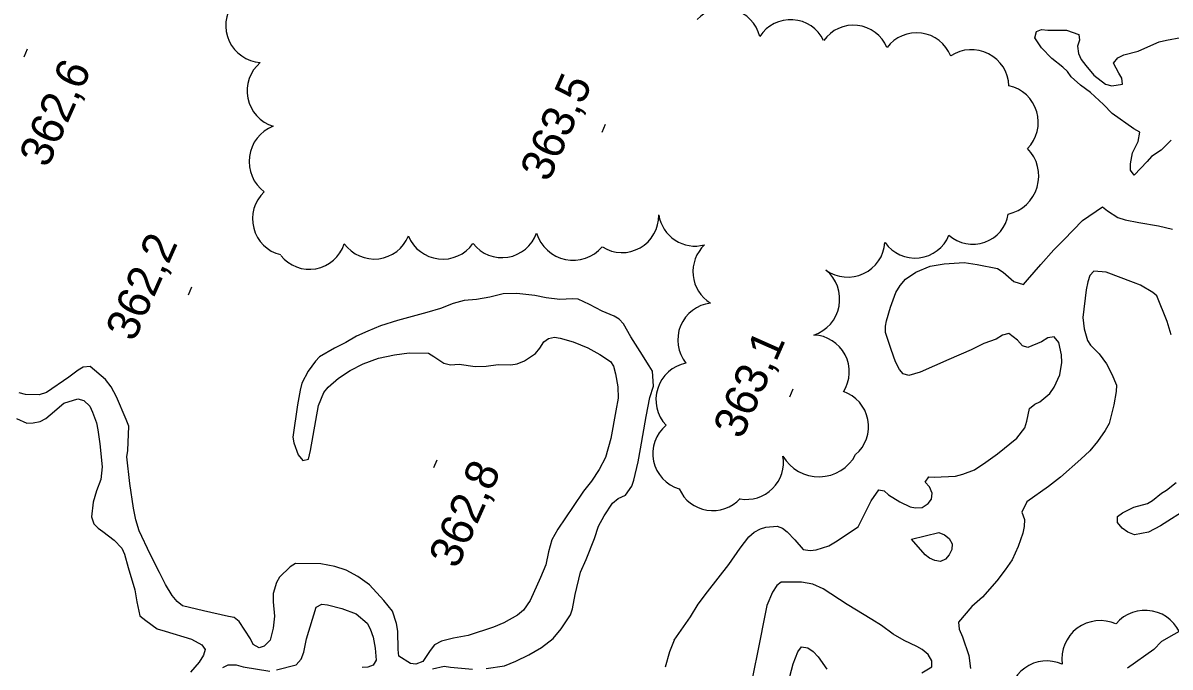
# Model space of a CAD drawing. Extents: x 287698 to 290158, y 5234163 to 5237182.
# Drawn here: x 288362.3 to 288468, y 5235647.2 to 5235706.5 of the extents above; entities that cross this region are included whole.
import ezdxf

# ---------------------------------------------------------------- set-up
doc = ezdxf.new("R2010")
doc.units = 0
for name, color, linetype in [('Niveau 2', 7, 'Continuous'), ('Niveau 3', 7, 'Continuous'), ('Niveau 4', 7, 'Continuous'), ('Niveau 44', 7, 'Continuous')]:
    doc.layers.add(name, color=color, linetype=linetype)

msp = doc.modelspace()

# ---------------------------------------------------------------- linework, layer by layer
at = {"layer": 'Niveau 2'}
msp.add_lwpolyline([(288469.5, 5235650.87), (288467.24, 5235649.57), (288466.54, 5235648.86), (288464.11, 5235647.14)], dxfattribs=at)
at = {"layer": 'Niveau 3'}
for p, q in [((288362.44, 5235703.42), (288362.76, 5235704.15)), ((288415.68, 5235696.48), (288416, 5235697.21)), ((288377.57, 5235681.51), (288377.89, 5235682.24)), ((288432.98, 5235672.11), (288433.3, 5235672.84)), ((288400.17, 5235665.59), (288400.49, 5235666.32))]:
    msp.add_line(p, q, dxfattribs=at)
at = {"layer": 'Niveau 4'}
for points in [[(288468.13, 5235695.73), (288467.19, 5235694.83), (288466.3, 5235694.24), (288465.92, 5235693.77), (288464.7, 5235692.52), (288464.39, 5235692.97), (288464.38, 5235693.55), (288464.57, 5235694.58), (288465.07, 5235695.61), (288465.22, 5235696.48), (288464.68, 5235696.8), (288462.68, 5235698.19), (288461.89, 5235699.03), (288460.7, 5235700.13), (288459.78, 5235700.81), (288458.92, 5235701.57), (288458.58, 5235702.05), (288458.14, 5235702.45), (288457.12, 5235703.26), (288456.17, 5235704.23), (288455.56, 5235705.15), (288455.7, 5235705.74), (288456.18, 5235705.92), (288456.77, 5235705.87), (288458.49, 5235705.87), (288459.63, 5235705.48), (288459.67, 5235704.94), (288459.5, 5235704.4), (288459.57, 5235703.73), (288459.84, 5235703.18), (288460.25, 5235702.62), (288461, 5235701.74), (288462.08, 5235700.89), (288462.67, 5235700.75), (288463.64, 5235700.89), (288463.58, 5235701.46), (288463.31, 5235701.92), (288462.82, 5235702.83), (288463.2, 5235703.33), (288463.77, 5235703.59), (288465.09, 5235703.94), (288465.71, 5235704.22), (288467.01, 5235704.79), (288467.68, 5235704.95), (288469.02, 5235705.18)], [(288422.34, 5235649.71), (288423.83, 5235651.85), (288424.53, 5235653.01), (288425.41, 5235654.15), (288427.36, 5235656.67), (288428.41, 5235658.19), (288429.21, 5235659.22), (288429.7, 5235659.64), (288430.27, 5235659.95), (288430.78, 5235660.1), (288431.82, 5235660.21), (288432.32, 5235660.03), (288432.75, 5235659.69), (288433.45, 5235658.93), (288434.2, 5235658.06), (288434.86, 5235657.96), (288435.4, 5235658.01), (288436.57, 5235658.38), (288437.2, 5235658.75), (288439.27, 5235660.15), (288439.54, 5235660.63), (288440.47, 5235662.53), (288441.2, 5235663.56), (288441.69, 5235663.44), (288442.08, 5235663.1), (288443.12, 5235662.45), (288444.06, 5235661.97), (288444.57, 5235661.89), (288445.17, 5235661.93), (288445.73, 5235662.29), (288446.04, 5235662.7), (288446.09, 5235663.23), (288445.84, 5235663.82), (288445.47, 5235664.26), (288445.78, 5235664.74), (288446.28, 5235664.72), (288448.25, 5235664.79), (288448.93, 5235664.98), (288449.99, 5235665.4), (288451.05, 5235666.08), (288452.13, 5235666.86), (288453.91, 5235668.29), (288454.64, 5235669.27), (288454.82, 5235669.87), (288455.07, 5235671.02), (288455.55, 5235671.42), (288456.03, 5235671.64), (288456.94, 5235672.43), (288457.33, 5235672.99), (288457.86, 5235674.14), (288458.04, 5235675.28), (288458.01, 5235675.99), (288457.77, 5235677.12), (288457.35, 5235677.62), (288456.76, 5235677.55), (288456.16, 5235677.18), (288454.93, 5235676.66), (288454.42, 5235676.81), (288453.95, 5235677.33), (288453.15, 5235677.95), (288452.58, 5235677.78), (288452, 5235677.42), (288450.86, 5235677.02), (288449.7, 5235676.45), (288447.64, 5235675.55), (288445, 5235674.39), (288443.96, 5235674.07), (288443.42, 5235674.24), (288443.09, 5235674.64), (288442.73, 5235675.32), (288442.32, 5235676.46), (288441.81, 5235678.03), (288441.79, 5235678.62), (288441.9, 5235679.11), (288442.26, 5235680.38), (288442.75, 5235681.72), (288443.14, 5235682.36), (288443.64, 5235682.93), (288444.59, 5235683.6), (288445.93, 5235684.15), (288447.21, 5235684.36), (288449.06, 5235684.48), (288450.26, 5235684.29), (288452.12, 5235683.91), (288452.63, 5235683.6), (288453.62, 5235682.74), (288454.52, 5235682.45), (288454.9, 5235682.87), (288456.1, 5235684.29), (288457.3, 5235685.64), (288458.23, 5235686.57), (288459.94, 5235688.35), (288461.78, 5235689.59), (288462.25, 5235689.23), (288463.2, 5235688.63), (288463.89, 5235688.42), (288465.14, 5235688.15), (288466.96, 5235687.84), (288468.24, 5235687.54)], [(288468.12, 5235677.81), (288467.74, 5235679.04), (288466.81, 5235681.4), (288466.42, 5235681.73), (288465.3, 5235682.39), (288464.65, 5235682.63), (288462.13, 5235683.58), (288461.01, 5235683.69), (288460.63, 5235683.29), (288460.43, 5235682.7), (288460.3, 5235681.96), (288459.98, 5235679.4), (288460.12, 5235678.36)], [(288405.01, 5235647.09), (288406.7, 5235647.35), (288407.75, 5235647.77), (288408.95, 5235648.36), (288410.11, 5235649.04), (288411.18, 5235649.87), (288411.92, 5235650.76), (288412.79, 5235652.04), (288412.96, 5235652.58), (288413.2, 5235653.9), (288413.69, 5235655.98), (288414.21, 5235657.14), (288415, 5235659.06), (288415.36, 5235660.19), (288415.87, 5235661.16), (288416.66, 5235662.32), (288417.16, 5235662.74), (288417.83, 5235663.06), (288418.43, 5235663.88), (288418.6, 5235664.45), (288419.01, 5235666.13), (288419.22, 5235667.31), (288419.74, 5235670.3), (288420.08, 5235672.05), (288420.41, 5235673.1), (288420.34, 5235674.46), (288420.02, 5235674.95), (288419.21, 5235676.29), (288418.33, 5235677.64), (288417.67, 5235678.83), (288417.25, 5235679.27), (288416.81, 5235679.53), (288415.7, 5235679.99), (288414.53, 5235680.62), (288413.48, 5235681.09), (288412.96, 5235681.14), (288411.78, 5235681.07), (288410.54, 5235681.22), (288409.49, 5235681.43), (288407.83, 5235681.62), (288406.58, 5235681.58), (288405.36, 5235681.29), (288404.13, 5235681.07), (288402.98, 5235680.99), (288401.98, 5235680.69), (288400.8, 5235680.23)], [(288400.8, 5235680.23), (288399.53, 5235679.87), (288396.83, 5235679.14), (288395.28, 5235678.64), (288394.09, 5235678.17), (288393.07, 5235677.69), (288392.09, 5235677.1), (288391.03, 5235676.6), (288389.64, 5235675.79), (288389.27, 5235675.4), (288388.6, 5235674.48), (288388.02, 5235673.36), (288387.87, 5235672.73), (288387.63, 5235671.37), (288387.19, 5235668.39), (288387.28, 5235667.86), (288387.67, 5235666.78), (288388.12, 5235666.26), (288388.65, 5235666.38), (288388.82, 5235667.16), (288389.06, 5235668.54), (288389.56, 5235671.32), (288390.06, 5235672.52), (288390.46, 5235673.01), (288391.4, 5235673.82), (288392.47, 5235674.53), (288393.68, 5235675.16), (288395.09, 5235675.66), (288396.57, 5235675.98), (288397.9, 5235676.15), (288399.69, 5235676.12), (288400.2, 5235675.83), (288401.11, 5235675.2), (288401.72, 5235675.07), (288402.53, 5235675.11), (288403.98, 5235674.89), (288405, 5235674.93), (288406.12, 5235675.1), (288407.27, 5235675.05), (288407.87, 5235675.15), (288408.53, 5235675.42), (288409.55, 5235676.11), (288409.96, 5235676.58), (288410.33, 5235677.18), (288410.75, 5235677.48), (288411.29, 5235677.61), (288411.84, 5235677.51), (288413.03, 5235677.18), (288414.37, 5235676.62), (288415.49, 5235676.02), (288416.47, 5235675.37), (288416.73, 5235674.94), (288416.91, 5235674.24), (288417.13, 5235673.03), (288417.16, 5235671.98), (288416.95, 5235670.82), (288416.5, 5235668.27), (288416, 5235666.51), (288415.41, 5235665.42), (288414.72, 5235664.34), (288413.97, 5235663.42), (288413.03, 5235662.02), (288411.61, 5235659.94), (288411.05, 5235658.93), (288410.75, 5235657.84), (288410.5, 5235656.63), (288410, 5235655.46), (288409.06, 5235653.35), (288408.46, 5235652.48), (288407.88, 5235652), (288406.64, 5235651.31), (288405.67, 5235650.91), (288403.35, 5235650.12), (288402, 5235649.88), (288400.88, 5235649.61), (288400.24, 5235649.29), (288399.86, 5235648.74), (288399.18, 5235647.74), (288398.52, 5235647.5), (288398.02, 5235647.57), (288396.95, 5235648.23), (288396.91, 5235648.86), (288396.87, 5235650.52), (288396.74, 5235651.23), (288396.39, 5235652.38), (288395.57, 5235653.35), (288394.25, 5235654.79), (288393.17, 5235655.56), (288392.12, 5235656.15), (288391.06, 5235656.49), (288389.77, 5235656.72), (288387.44, 5235656.75), (288386.94, 5235656.46), (288385.95, 5235655.49), (288385.68, 5235655), (288385.38, 5235654.01), (288385.37, 5235653.22), (288385.5, 5235651.92), (288385.37, 5235650.82), (288385.1, 5235649.7), (288384.56, 5235649.15)], [(288460.12, 5235678.36), (288460.41, 5235677.31), (288460.7, 5235676.87), (288461.49, 5235676.08), (288462.17, 5235675.16), (288462.67, 5235674.21), (288463.09, 5235673.18), (288463.05, 5235672.61), (288462.83, 5235671.36), (288462.4, 5235669.65), (288462.03, 5235669), (288461.34, 5235667.99), (288460.63, 5235667.14), (288459.79, 5235666.36), (288457.93, 5235664.72), (288456.82, 5235663.86), (288454.82, 5235662.44), (288454.36, 5235661.49), (288454.61, 5235660.81), (288454.59, 5235660.18), (288454.44, 5235659.55), (288454.02, 5235658.33), (288453.46, 5235657.1), (288452.83, 5235656.17), (288452.05, 5235655.18), (288450.75, 5235653.65), (288449.75, 5235652.79), (288448.53, 5235651.35), (288448.59, 5235650.73), (288448.89, 5235650.01), (288449.49, 5235648.3), (288449.62, 5235647.09)], [(288384.56, 5235649.15), (288384.08, 5235649), (288383.55, 5235649.3), (288383.28, 5235649.83), (288382.26, 5235651.41), (288381.79, 5235651.8), (288381.27, 5235651.89), (288378.96, 5235652.4), (288377.02, 5235652.88), (288376.54, 5235653.25), (288376.07, 5235653.83), (288375.45, 5235654.84), (288374.92, 5235655.95), (288374.05, 5235657.63), (288373.05, 5235659.77), (288372.73, 5235660.77), (288372.51, 5235661.87), (288372.17, 5235664.14), (288371.91, 5235666.59), (288372, 5235667.16), (288372.08, 5235669.42), (288371.84, 5235670.02), (288370.94, 5235672.1), (288370.44, 5235673.04), (288369.94, 5235673.7), (288368.53, 5235674.91), (288367.88, 5235674.85), (288367.41, 5235674.56), (288366.55, 5235673.91), (288364.51, 5235672.51), (288363.82, 5235672.29), (288362.57, 5235672.31), (288361.98, 5235672.49)], [(288364.82, 5235670.45), (288366.1, 5235671.53), (288367.37, 5235671.91), (288367.93, 5235671.77), (288368.48, 5235671.26), (288368.75, 5235670.69), (288369.1, 5235669.72), (288369.24, 5235669.07), (288369.4, 5235667.78), (288369.62, 5235665.65), (288369.49, 5235664.49), (288369.09, 5235663.44), (288368.81, 5235662.4), (288368.64, 5235661.06), (288368.87, 5235660.42), (288369.26, 5235660.01), (288369.68, 5235659.72), (288370.73, 5235658.92), (288371.45, 5235658.16), (288371.69, 5235657.63), (288372.02, 5235656.38), (288372.63, 5235654.34), (288372.83, 5235653.24), (288373.1, 5235651.93), (288373.64, 5235651.51), (288374.68, 5235650.74), (288375.42, 5235650.53), (288377.87, 5235649.81), (288378.82, 5235649.26), (288379.11, 5235648.84), (288378.97, 5235648.32), (288378.57, 5235647.67), (288377.75, 5235646.76)], [(288361.74, 5235670.12), (288362.7, 5235669.69), (288363.28, 5235669.7), (288363.91, 5235669.83), (288364.43, 5235670.1), (288364.82, 5235670.45)], [(288469.76, 5235661.9), (288467.14, 5235660.23), (288466.02, 5235659.65), (288464.73, 5235659.39), (288464.14, 5235659.66), (288463.62, 5235660.02), (288463.18, 5235660.53), (288463.17, 5235661.09), (288463.63, 5235661.43), (288464.68, 5235661.95), (288465.94, 5235662.28), (288466.39, 5235662.56), (288467.22, 5235663.23), (288467.68, 5235663.51), (288468.59, 5235664.21)], [(288444.21, 5235658.99), (288446.7, 5235659.63), (288447.24, 5235659.4), (288447.66, 5235659.08), (288447.95, 5235658.56), (288447.9, 5235658.04), (288447.66, 5235657.55), (288447.32, 5235657.16), (288446.87, 5235656.94), (288446.34, 5235657.04), (288445.87, 5235657.25), (288445.47, 5235657.57), (288444.21, 5235658.99)], [(288445.16, 5235646.69), (288446.06, 5235647.26), (288446.06, 5235647.81), (288445.74, 5235648.37), (288445.18, 5235648.84), (288444.69, 5235649.11), (288443.53, 5235649.66), (288442.52, 5235650.26), (288441.43, 5235651.07), (288440.53, 5235651.61), (288438.26, 5235652.99), (288436.07, 5235654.44), (288435.11, 5235654.87), (288434.05, 5235655.06), (288432.19, 5235655.05), (288431.8, 5235654.73), (288431.4, 5235654.12), (288430.87, 5235652.9), (288430.65, 5235651.83), (288430.16, 5235649.34), (288429.53, 5235646.15)], [(288385.68, 5235646.97), (288387.49, 5235647.43), (288387.96, 5235647.97), (288388.21, 5235648.61), (288388.46, 5235649.84), (288389.33, 5235652.75), (288389.86, 5235653.02), (288390.38, 5235652.97), (288391.7, 5235652.63), (288393.02, 5235652.12), (288394.03, 5235651.28), (288394.33, 5235650.75), (288394.59, 5235649.98), (288394.77, 5235648.97), (288394.86, 5235647.86), (288394.61, 5235647.39), (288394.1, 5235647.23), (288393.58, 5235647.2)], [(288422.34, 5235649.71), (288421.9, 5235648.62), (288421.51, 5235647.22)], [(288432.98, 5235646.36), (288433.3, 5235647.54), (288433.72, 5235648.62), (288434.07, 5235649.09), (288434.65, 5235649), (288435.13, 5235648.67), (288435.59, 5235648.18), (288436.41, 5235647.04)], [(288380.73, 5235647.18), (288381.24, 5235647.44), (288381.98, 5235647.44), (288382.61, 5235647.26), (288385.08, 5235646.85)], [(288400.07, 5235647.05), (288401.13, 5235647.3), (288401.73, 5235647.23), (288403.76, 5235647.04)]]:
    msp.add_lwpolyline(points, dxfattribs=at)
at = {"layer": 'Niveau 44'}
msp.add_arc((288433.06, 5235703.47), 3.37, 25.5116, 147.275, dxfattribs=at)
for centre, major_axis, ratio, start_param, end_param in [((288384.44, 5235706.31), (-3.11, -1.44), 0.999994, 5.220593, 7.346989), ((288426.89, 5235704.46), (1.17, 3.23), 0.999384, 5.303084, 7.426184), ((288438.84, 5235702.97), (1.42, 3.04), 0.99996, 5.543953, 7.672692), ((288444.66, 5235702.24), (1.5, 3.04), 0.99996, 5.547955, 7.67314), ((288449.73, 5235700.63), (1.57, 3.07), 0.999555, 5.219472, 7.345711), ((288386.41, 5235700.28), (2.28, -2.55), 0.999995, 3.115335, 5.245267), ((288452.42, 5235697.38), (3.45, 0.17), 0.999929, 5.462277, 7.583508), ((288386.65, 5235693.77), (-3.25, 1.27), 0.99993, 5.459798, 7.585393), ((288452.31, 5235692.45), (3.43, -1.14), 0.997223, 5.254688, 7.37899), ((288386.87, 5235688.49), (-3.39, 0.09), 0.99881, 5.488082, 7.640889), ((288417.52, 5235688.78), (2.95, 1.67), 0.999937, 3.635654, 5.789124), ((288424.26, 5235689.38), (-1.94, -2.78), 0.999335, 5.479567, 7.148507), ((288449.84, 5235689.48), (0.58, 3.27), 0.999982, 2.596579, 4.721392), ((288394.69, 5235688.21), (-0.4, -3.39), 0.999927, 5.459758, 7.585165), ((288401.01, 5235688.21), (3.13, 1.38), 0.999995, 3.115224, 5.245506), ((288406.46, 5235688.32), (2.61, 2.17), 0.999994, 3.116001, 5.244449), ((288413.03, 5235688.23), (-1, -3.4), 0.999421, 5.302184, 7.425754), ((288444.52, 5235688.28), (0.37, -3.37), 0.999994, 5.220267, 7.351378), ((288388.72, 5235687.23), (0.09, -3.38), 0.997086, 5.355404, 7.517045), ((288427.45, 5235683.63), (-2.89, 1.78), 0.999478, 6.019209, 7.85191), ((288438.33, 5235686.56), (0.27, 3.42), 0.999983, 2.593704, 4.722362), ((288434.1, 5235681.1), (3.42, -0.64), 0.999978, 5.21934, 7.347434), ((288426.08, 5235677.35), (-3.09, 1.46), 0.998652, 5.273234, 7.401145), ((288435.07, 5235674.41), (3.37, 0.42), 0.999241, 5.588533, 7.693225), ((288424.09, 5235671.84), (-3.23, 1.19), 0.998303, 5.264776, 7.388739), ((288436.84, 5235669.37), (-0.72, 3.32), 0.999859, 3.634947, 5.746454), ((288423.75, 5235666.89), (-1.92, -2.79), 0.999732, 4.440494, 6.601324), ((288429, 5235666.06), (2.66, 2.11), 0.999937, 3.862737, 5.790236), ((288435.66, 5235668.59), (0.09, -3.84), 0.999131, 5.21638, 7.343179), ((288425.89, 5235665.02), (3.38, -0.25), 0.999984, 3.635019, 5.618636), ((288465.72, 5235648.95), (0.67, 3.44), 0.999233, 5.218109, 7.34552), ((288461.59, 5235647.96), (-2.13, 2.84), 0.999373, 5.219743, 7.344696), ((288456.65, 5235644.38), (-1.66, 2.99), 0.999759, 5.34752, 7.472498)]:
    msp.add_ellipse(centre, major_axis=major_axis, ratio=ratio, start_param=start_param, end_param=end_param, dxfattribs=at)

# ---------------------------------------------------------------- texts
at = {"layer": 'Niveau 3'}
for s, p in [('362,6', (288364.6, 5235693.1)), ('363,5', (288410.76, 5235691.79)), ('362,2', (288372.57, 5235677.09)), ('363,1', (288428.55, 5235668.11)), ('362,8', (288402.34, 5235656.18))]:
    msp.add_text(s, height=3, rotation=66.1217, dxfattribs=at).set_placement(p)

doc.saveas('drawing.dxf')
